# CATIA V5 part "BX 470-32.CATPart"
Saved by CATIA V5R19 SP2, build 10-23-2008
Part number: BX 470-32
Bounding box of the stored display mesh (mm): x -37.351 to 37.351, y -37.351 to 37.351, z 0 to 167
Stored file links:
  C:\Users\Bora\Desktop\3D Katı model\BX serisi\BX 470\BX 470-32.CATPart
  C:\Program Files\Dassault Systemes\B19\intel_a\reffiles\standard\MetricThickPitch.txt
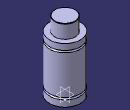
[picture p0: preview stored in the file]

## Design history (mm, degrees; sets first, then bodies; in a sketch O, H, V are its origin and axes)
Body1 (main body)
  Sketch1 on yz-plane, origin (0, 0, 0), H (0, 1, 0), V (0, 0, 1)
    point P1 (37.5, 114.5)
    point P2 (37.5, 119.5)
    arc A1 centre (37.5, 117) radius 2.5 from (37.5, 119.5) to (37.5, 114.5) ccw
    point P3 (37.5, 15.5)
    point P4 (37.5, 20.5)
    arc A2 centre (37.5, 18) radius 2.5 from (37.5, 20.5) to (37.5, 15.5) ccw
    point P5 (37.5, 119.5)
    line L1 (37.5, 134) -> (37.5, 119.5)
    point P8 (25, 166)
    line L2 (25, 166) -> (25, 134)
    point P10 (25, 166)
    arc A3 centre (24, 166) radius 1 from (25, 166) to (24, 167) ccw
    point P11 (37.5, 20.5)
    point P12 (37.5, 114.5)
    line L3 (37.5, 114.5) -> (37.5, 20.5)
    point P14 (37.5, 15.5)
    line L4 (37.5, 15.5) -> (37.5, 0)
    line L5 (24, 167) -> (0, 167)
    point P15 (0, 167)
    line L6 (37.5, 134) -> (25, 134)
    line L7 (37.5, 0) -> (0, 0)
    tangency: L5 A3
    coincidence: P15 V, P1 P12, P2 P5, P3 P14, P4 P11, P8 P10
    horizontal: L6 H, L7 H
  Shaft1: profile Sketch1, axis Sketch1.V, angle 360
  Sketch2 on face of Shaft1 from Sketch1.L7, origin (0, 0, 0), H (1, 0, 0), V (0, -1, 0)
    point P1 (20, 0)
    distance P1 V = 20
  Hole1: placed by Sketch2, at (20, 0, 0) direction (0, 0, 1), diameter 6.647, depth 7, threaded "M8", thread diameter 8, thread depth 7, pitch 1.25
  CircPattern1: of Hole1, instances 4, angular step 90, axis from xy-plane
